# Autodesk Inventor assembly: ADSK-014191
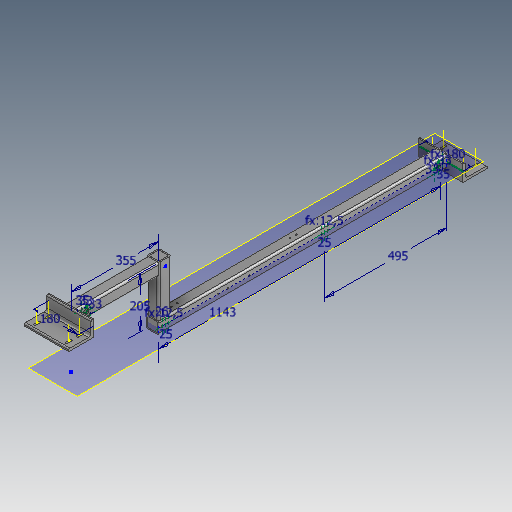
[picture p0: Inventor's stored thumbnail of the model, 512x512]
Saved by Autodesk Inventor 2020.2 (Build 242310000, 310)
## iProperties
Created: 1999-12
Part Number: ADSK-014191
Description: WMT-CP,TU,XX,MNT,PLOW,ADJUSTABLE
Document SubType Name: Assembly
Designer: sspink
Mass: 15989.1 g
Surface Area: 7123.65 cm^2
Volume: 2036.83 cm^3
Density: 7.85 g/cm^3
Control State: 0
Checked Out: False
Last Check In By: gpurviance
Last Check In Date: 2000-01-06
Master: False
Shininess: 0.0
Length Units: 11269
Angle Units: 11279
Time Units: 11290
Mass Units: 11283
Length Display Precision: 3
Angle Display Precision: 2
Compacted: True
_SolveAssemblyDoc: Frame Generator Solve Assembly
_Version: 15.0.0
Density: 0.0
Volumn: 0.0
Area: 0.0
PropertySet Name: Model Information
Dimensions: 270x1698x180 mm
Mass: 15,989 kg
DocNumber: 500277.iam
Folder: 01 - Themengebiete\Simplification\01 - Packaging machine\
VDS_Category: 3D Komponenten
Author: sspink
Revision Number: -
Title: 500277
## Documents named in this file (3)
- D:\07 - DEMODATEN\OTX 2019 - Dataset - UPDATE - Dez2019\Designs\07-Packing machine\ADSK-014191.iam
- D:\07 - DEMODATEN\OTX 2019 - Dataset - UPDATE - Dez2019\Designs\07-Packing machine\Parts\ADSK-014172.ipt
- D:\07 - DEMODATEN\OTX 2019 - Dataset - UPDATE - Dez2019\Designs\07-Packing machine\500277\Frame\ADSK-014192.iam
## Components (2 placed, 2 different names)
1. ADSK-014172:1 — Fluchtend:13, Fluchtend:14, Fluchtend:15
2. ADSK-014192:1 [sub-assembly]
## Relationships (3: Flush 3)
- Fluchtend:13 [Flush]: ADSK-014172:1
- Fluchtend:14 [Flush]: ADSK-014172:1
- Fluchtend:15 [Flush]: ADSK-014172:1
